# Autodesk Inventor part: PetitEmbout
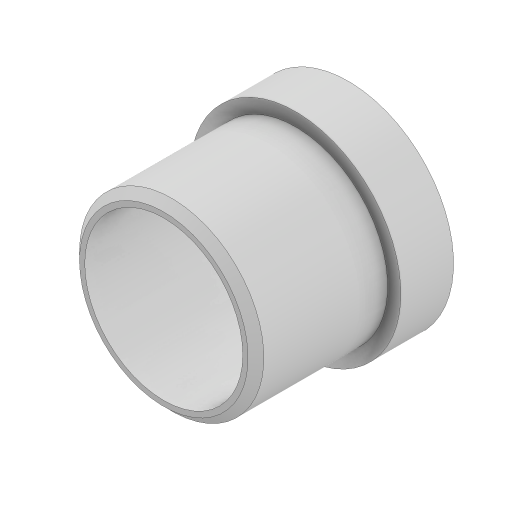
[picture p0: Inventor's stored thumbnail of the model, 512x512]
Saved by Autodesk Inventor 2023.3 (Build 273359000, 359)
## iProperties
Created: 2024-11
Part Number: PetitEmbout
Material: Générique
Description: STEP AP203
Document SubType Name: Modeling
Designer: Thier
Density: 1 g/cm^3
Appearance: Par défaut
Title: PetitEmbout.STEP
Revision Number: ANY
Sending System: SolidWorks 2017
Preprocessor: SwSTEP 2.0
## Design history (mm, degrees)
feature "Chanfrein1"
node "Solide1"
